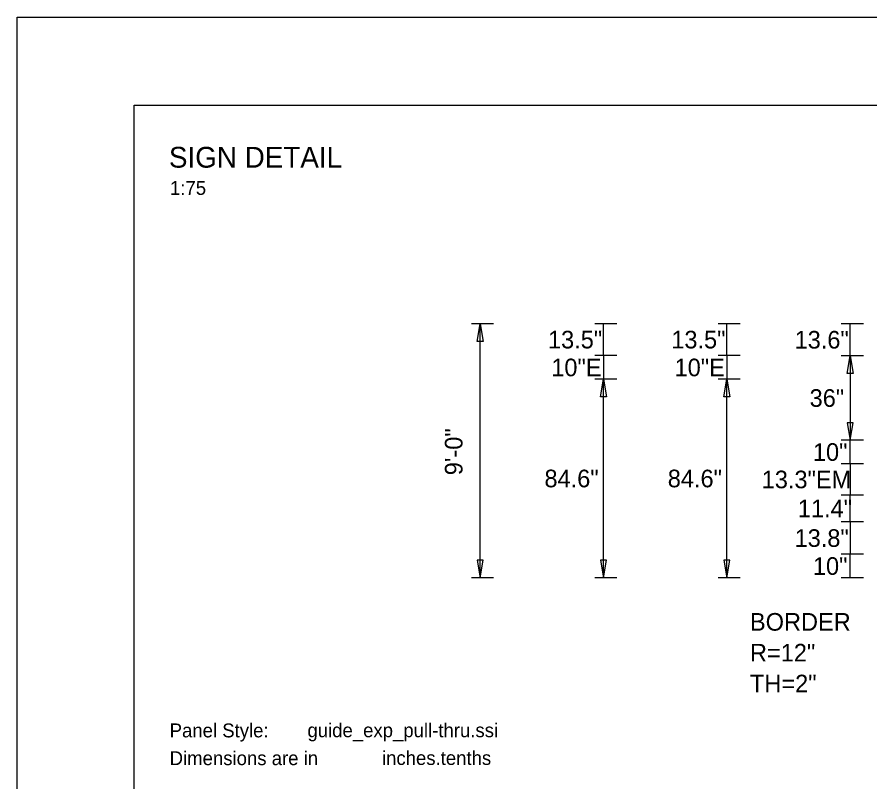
# Model space of a CAD drawing. Extents: x 1806251 to 1809821, y 414895 to 422886.
# Drawn here: x 1809672.135 to 1809675.767, y 414930.972 to 414934.227 of the extents above; entities that cross this region are included whole.
import ezdxf

# ---------------------------------------------------------------- set-up
doc = ezdxf.new("R2010")
doc.units = 0
doc.layers.add('GSDIMS', color=7, linetype='Continuous')
doc.layers.add('GSSHT', color=7, linetype='Continuous')

msp = doc.modelspace()

# ---------------------------------------------------------------- linework, layer by layer
at = {"layer": 'GSDIMS'}
for p, q in [((1809674.1638, 414932.922), (1809674.07, 414932.922)), ((1809674.1075, 414931.841), (1809674.1075, 414932.922)), ((1809674.6887, 414932.922), (1809674.595, 414932.922)), ((1809674.6325, 414932.7866), (1809674.6325, 414932.922)), ((1809675.2138, 414932.922), (1809675.12, 414932.922)), ((1809675.1575, 414932.7866), (1809675.1575, 414932.922)), ((1809675.7388, 414932.922), (1809675.645, 414932.922)), ((1809675.6825, 414932.786), (1809675.6825, 414932.922)), ((1809674.6887, 414932.7866), (1809674.595, 414932.7866)), ((1809674.6887, 414932.7866), (1809674.595, 414932.7866)), ((1809674.6325, 414932.7866), (1809674.6325, 414932.6866)), ((1809675.2138, 414932.7866), (1809675.12, 414932.7866)), ((1809675.2138, 414932.7866), (1809675.12, 414932.7866)), ((1809675.1575, 414932.7866), (1809675.1575, 414932.6866)), ((1809675.7388, 414932.786), (1809675.645, 414932.786)), ((1809675.7388, 414932.786), (1809675.645, 414932.786)), ((1809675.6825, 414932.786), (1809675.6825, 414932.426)), ((1809674.6887, 414932.6866), (1809674.595, 414932.6866)), ((1809674.6887, 414932.6866), (1809674.595, 414932.6866)), ((1809674.6325, 414931.841), (1809674.6325, 414932.6866)), ((1809675.2138, 414932.6866), (1809675.12, 414932.6866)), ((1809675.2138, 414932.6866), (1809675.12, 414932.6866)), ((1809675.1575, 414931.841), (1809675.1575, 414932.6866)), ((1809675.7388, 414932.426), (1809675.645, 414932.426)), ((1809675.7388, 414932.426), (1809675.645, 414932.426)), ((1809675.6825, 414932.3262), (1809675.6825, 414932.426)), ((1809675.7388, 414932.3262), (1809675.645, 414932.3262)), ((1809675.7388, 414932.3262), (1809675.645, 414932.3262)), ((1809675.6825, 414932.3262), (1809675.6825, 414932.1932)), ((1809675.7388, 414932.1932), (1809675.645, 414932.1932)), ((1809675.7388, 414932.1932), (1809675.645, 414932.1932)), ((1809675.6825, 414932.079), (1809675.6825, 414932.1932)), ((1809675.7388, 414932.079), (1809675.645, 414932.079)), ((1809675.7388, 414932.079), (1809675.645, 414932.079)), ((1809675.6825, 414932.079), (1809675.6825, 414931.941)), ((1809675.7388, 414931.941), (1809675.645, 414931.941)), ((1809675.7388, 414931.941), (1809675.645, 414931.941)), ((1809675.6825, 414931.841), (1809675.6825, 414931.941)), ((1809674.1638, 414931.841), (1809674.07, 414931.841)), ((1809674.6887, 414931.841), (1809674.595, 414931.841)), ((1809675.2138, 414931.841), (1809675.12, 414931.841)), ((1809675.7388, 414931.841), (1809675.645, 414931.841))]:
    msp.add_line(p, q, dxfattribs=at)
for points in [[(1809674.1075, 414932.922), (1809674.12, 414932.847), (1809674.095, 414932.847)], [(1809675.6825, 414932.786), (1809675.695, 414932.711), (1809675.67, 414932.711)], [(1809674.6325, 414932.6866), (1809674.645, 414932.6116), (1809674.62, 414932.6116)], [(1809675.1575, 414932.6866), (1809675.17, 414932.6116), (1809675.145, 414932.6116)], [(1809675.6825, 414932.426), (1809675.695, 414932.501), (1809675.67, 414932.501)], [(1809674.1075, 414931.841), (1809674.12, 414931.916), (1809674.095, 414931.916)], [(1809674.6325, 414931.841), (1809674.645, 414931.916), (1809674.62, 414931.916)], [(1809675.1575, 414931.841), (1809675.17, 414931.916), (1809675.145, 414931.916)]]:
    msp.add_lwpolyline(points, close=True, dxfattribs=at)
at = {"layer": 'GSSHT'}
for p, q in [((1809672.1353, 414934.2272), (1809684.8895, 414934.2272)), ((1809672.1353, 414925.9734), (1809672.1353, 414934.2272))]:
    msp.add_line(p, q, dxfattribs=at)
msp.add_lwpolyline([(1809672.6344, 414933.8521), (1809684.6385, 414933.8521), (1809684.6385, 414926.3484), (1809672.6344, 414926.3484)], close=True, dxfattribs=at)

# ---------------------------------------------------------------- texts
at = {"layer": 'GSDIMS'}
for s, p in [('13.5"', (1809674.396, 414932.8171)), ('13.5"', (1809674.921, 414932.8171)), ('13.6"', (1809675.446, 414932.8165)), ('10"E', (1809674.41, 414932.6986)), ('10"E', (1809674.935, 414932.6986)), ('36"', (1809675.51, 414932.5685)), ('10"', (1809675.524, 414932.3387)), ('84.6"', (1809674.381, 414932.2261)), ('84.6"', (1809674.906, 414932.2261)), ('13.3"EM', (1809675.306, 414932.222)), ('11.4"', (1809675.46, 414932.0987)), ('13.8"', (1809675.446, 414931.9725)), ('10"', (1809675.524, 414931.8535)), ('BORDER', (1809675.256, 414931.616)), ('R=12"', (1809675.256, 414931.4848)), ('TH=2"', (1809675.256, 414931.3535))]:
    msp.add_text(s, height=0.075, dxfattribs=at).set_placement(p)
msp.add_text('9\'-0"', height=0.075, rotation=90, dxfattribs=at).set_placement((1809674.032, 414932.2775))
at = {"layer": 'GSSHT'}
for s, height, p in [('SIGN DETAIL', 0.088592, (1809672.782, 414933.5863)), ('1:75', 0.05903, (1809672.7866, 414933.4705)), ('Panel Style:', 0.059061, (1809672.785, 414931.1619)), ('guide_exp_pull-thru.ssi', 0.059025, (1809673.3718, 414931.1626)), ('Dimensions are in', 0.059061, (1809672.785, 414931.0438)), ('inches.tenths', 0.059025, (1809673.6891, 414931.0446))]:
    msp.add_text(s, height=height, dxfattribs=at).set_placement(p)

doc.saveas('drawing.dxf')
